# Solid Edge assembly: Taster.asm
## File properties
Author: Heike
Template: Normal.asm
Last saved by: Heike
Revision: 1
Application: Solid Edge
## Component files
Rahmen.par
Deckel.par
Taste.par
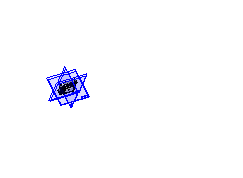
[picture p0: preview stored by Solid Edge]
